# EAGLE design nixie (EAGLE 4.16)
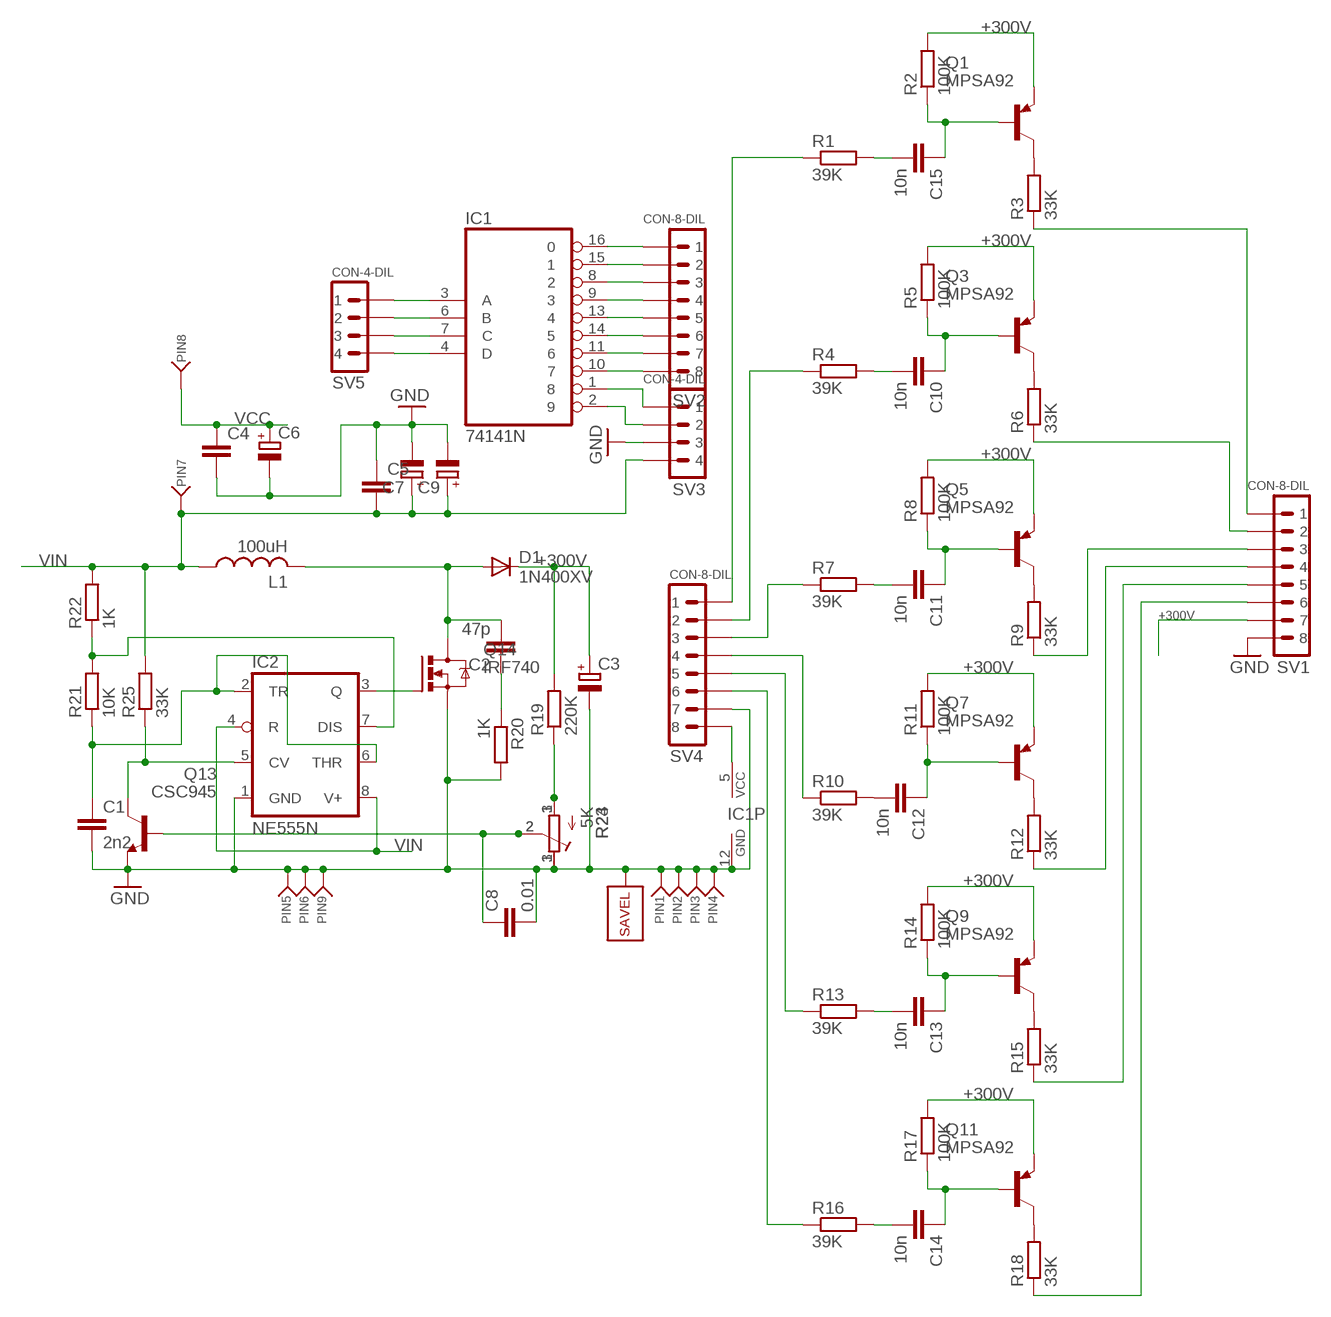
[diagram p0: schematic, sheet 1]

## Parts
C1  2n2  C-EUC0805K  [C0805K]
C2  47p  C-EU050-025X075  [C050-025X075]
C3  CPOL-EUE5-6  [E5-6]
C4  C-EUC0805K  [C0805K]
C5  C-EUC0805K  [C0805K]
C6  CPOL-EUE3.5-8  [E3,5-8]
C7  CPOL-EUE5-6  [E5-6]
C8  0.01  C-EUC0805K  [C0805K]
C9  CPOL-EUE3.5-8  [E3,5-8]
C10  10n  C-EU050-025X075  [C050-025X075]
C11  10n  C-EU050-025X075  [C050-025X075]
C12  10n  C-EU050-025X075  [C050-025X075]
C13  10n  C-EU050-025X075  [C050-025X075]
C14  10n  C-EU050-025X075  [C050-025X075]
C15  10n  C-EU050-025X075  [C050-025X075]
D1  1N400XV  [DO47-V]
IC1  74141N  [DIL16]
IC2  NE555N  [DIL08]
L1  100uH  L-US0204/7  [0204/7]
PIN1  PIN3.2  [3.2MM]
PIN2  PIN3.2  [3.2MM]
PIN3  PIN3.2  [3.2MM]
PIN4  PIN3.2  [3.2MM]
PIN5  PIN07  [PIN07]
PIN6  PINTERM_OFF  [PIN07_TERM_OFF]
PIN7  PIN07  [PIN07]
PIN8  PIN07  [PIN07]
PIN9  PINTERM_OFF  [PIN07_TERM_OFF]
Q1  MPSA92  [TO-92A]
Q3  MPSA92  [TO-92A]
Q5  MPSA92  [TO-92A]
Q7  MPSA92  [TO-92A]
Q9  MPSA92  [TO-92A]
Q11  MPSA92  [TO-92A]
Q13  CSC945  [TO-92T]
Q14  IRF740  [TO220BV]
R1  39K  R-EU_R0805  [R0805]
R2  100K  R-EU_R0805  [R0805]
R3  33K  R-EU_R0805  [R0805]
R4  39K  R-EU_R0805  [R0805]
R5  100K  R-EU_R0805  [R0805]
R6  33K  R-EU_R0805  [R0805]
R7  39K  R-EU_R0805  [R0805]
R8  100K  R-EU_R0805  [R0805]
R9  33K  R-EU_R0805  [R0805]
R10  39K  R-EU_R0805  [R0805]
R11  100K  R-EU_R0805  [R0805]
R12  33K  R-EU_R0805  [R0805]
R13  39K  R-EU_R0805  [R0805]
R14  100K  R-EU_R0805  [R0805]
R15  33K  R-EU_R0805  [R0805]
R16  39K  R-EU_R0805  [R0805]
R17  100K  R-EU_R0805  [R0805]
R18  33K  R-EU_R0805  [R0805]
R19  220K  R-EU_0204/2V  [0204V]
R20  1K  R-EU_R0805  [R0805]
R21  10K  R-EU_R0805  [R0805]
R22  1K  R-EU_R0805  [R0805]
R23  R-TRIMM3339P  [RTRIM3339P]
R24  5K  R-TRIMMT93YA  [RTRIMT93YA]
R25  33K  R-EU_R0805  [R0805]
SV1  CON-8-DIL  [CON-8-DIL-1]
SV2  CON-8-DIL  [CON-8-DIL-1]
SV3  CON-4-DIL  [CON-4-DIL-1]
SV4  CON-8-DIL  [CON-8-DIL-1]
SV5  CON-4-DIL  [CON-4-DIL-1]
U$2  SAVEL  [SAVEL]

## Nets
+300V: C3.+ D1.C Q1.E Q3.E Q5.E Q7.E Q9.E Q11.E R2.2 R5.2 R8.2 R11.2 R14.2 R17.2 R19.2 SV1.P$7
GND: C1.2 C3.- C4.2 C5.1 C6.- C7.- C8.2 C9.- IC1.12(GND) IC2.1(GND) PIN1.P$1(P) PIN2.P$1(P) PIN3.P$1(P) PIN4.P$1(P) PIN5.P$1(P) PIN6.P$1(P) PIN9.P$1(P) Q13.E Q14.S R20.2 R23.3(A) R24.1(A) SV1.P$8 SV3.P$3 SV4.P$7 U$2.P$1(A)
N$1: C15.1 Q1.B R2.1
N$2: C15.2 R1.2
N$3: IC2.3(Q) Q14.G
N$4: Q1.C R3.2
N$5: C10.1 Q3.B R5.1
N$6: C10.2 R4.2
N$7: IC2.5(CV) Q13.C R25.1
N$8: Q3.C R6.2
N$9: C11.1 Q5.B R8.1
N$10: C11.2 R7.2
N$11: C2.2 D1.A L1.2 Q14.D
N$12: Q5.C R9.2
N$13: C12.1 Q7.B R11.1
N$14: C12.2 R10.2
N$15: C2.1 R20.1
N$16: Q7.C R12.2
N$17: C13.1 Q9.B R14.1
N$18: C13.2 R13.2
N$19: IC2.7(DIS) R21.2 R22.1
N$20: Q9.C R15.2
N$21: C14.1 Q11.B R17.1
N$22: C14.2 R16.2
N$23: R19.1 R23.1(E) R24.3(E)
N$24: Q11.C R18.2
N$25: C1.1 IC2.2(TR) IC2.6(THR) R21.1
N$26: C8.1 Q13.B R23.2(S) R24.2(S)
N$27: R3.1 SV1.P$1
N$28: R6.1 SV1.P$2
N$29: R9.1 SV1.P$3
N$30: R12.1 SV1.P$4
N$31: R15.1 SV1.P$5
N$32: R18.1 SV1.P$6
N$33: IC1.16 SV2.P$1
N$34: IC1.15 SV2.P$2
N$35: IC1.8 SV2.P$3
N$36: IC1.9 SV2.P$4
N$37: IC1.13 SV2.P$5
N$38: IC1.14 SV2.P$6
N$39: IC1.11 SV2.P$7
N$40: IC1.10 SV2.P$8
N$41: IC1.1 SV3.P$1
N$42: IC1.2 SV3.P$2
N$43: R1.1 SV4.P$1
N$44: R4.1 SV4.P$2
N$45: R7.1 SV4.P$3
N$46: R10.1 SV4.P$4
N$47: R13.1 SV4.P$5
N$48: R16.1 SV4.P$6
N$49: IC1.3(A) SV5.P$1
N$50: IC1.6(B) SV5.P$2
N$51: IC1.7(C) SV5.P$3
N$52: IC1.4(D) SV5.P$4
VCC: C4.1 C6.+ IC1.5(VCC) PIN8.P$1(P) SV4.P$8
VIN: C5.2 C7.+ C9.+ IC2.4(R) IC2.8(V+) L1.1 PIN7.P$1(P) R22.2 R25.2 SV3.P$4

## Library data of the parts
C1 C2 C4 C5 C8 C10-C15 = rcl:C-EU: CAPACITOR, European symbol
C3 C6 C7 C9 = rcl:CPOL-EU: POLARIZED CAPACITOR, European symbol
D1 = LevoROMS:1N400X
IC1 = 74xx-eu:74*141: BCD to decimal DECODER/DRIVER
IC2 = linear:*555: TIMER
L1 = rcl:L-US: INDUCTOR, American symbol
PIN1-PIN9 = LevoROMS:PIN*: PIN
Q1 Q3 Q5 Q7 Q9 Q11 = LevoROMS:MPSA92
Q13 = LevoROMS:CSC945
Q14 = transistor-power:IRF740: N-CHANNEL MOS FET
R1-R22 R25 = rcl:R-EU_: RESISTOR, European symbol
R23 R24 = rcl:R-TRIMM: Trimm resistor
SV1 SV2 SV4 = LevoROMS:CON-8-DIL
SV3 SV5 = LevoROMS:CON-4-DIL
U$2 = LevoROMS:SAVEL: SAVEL

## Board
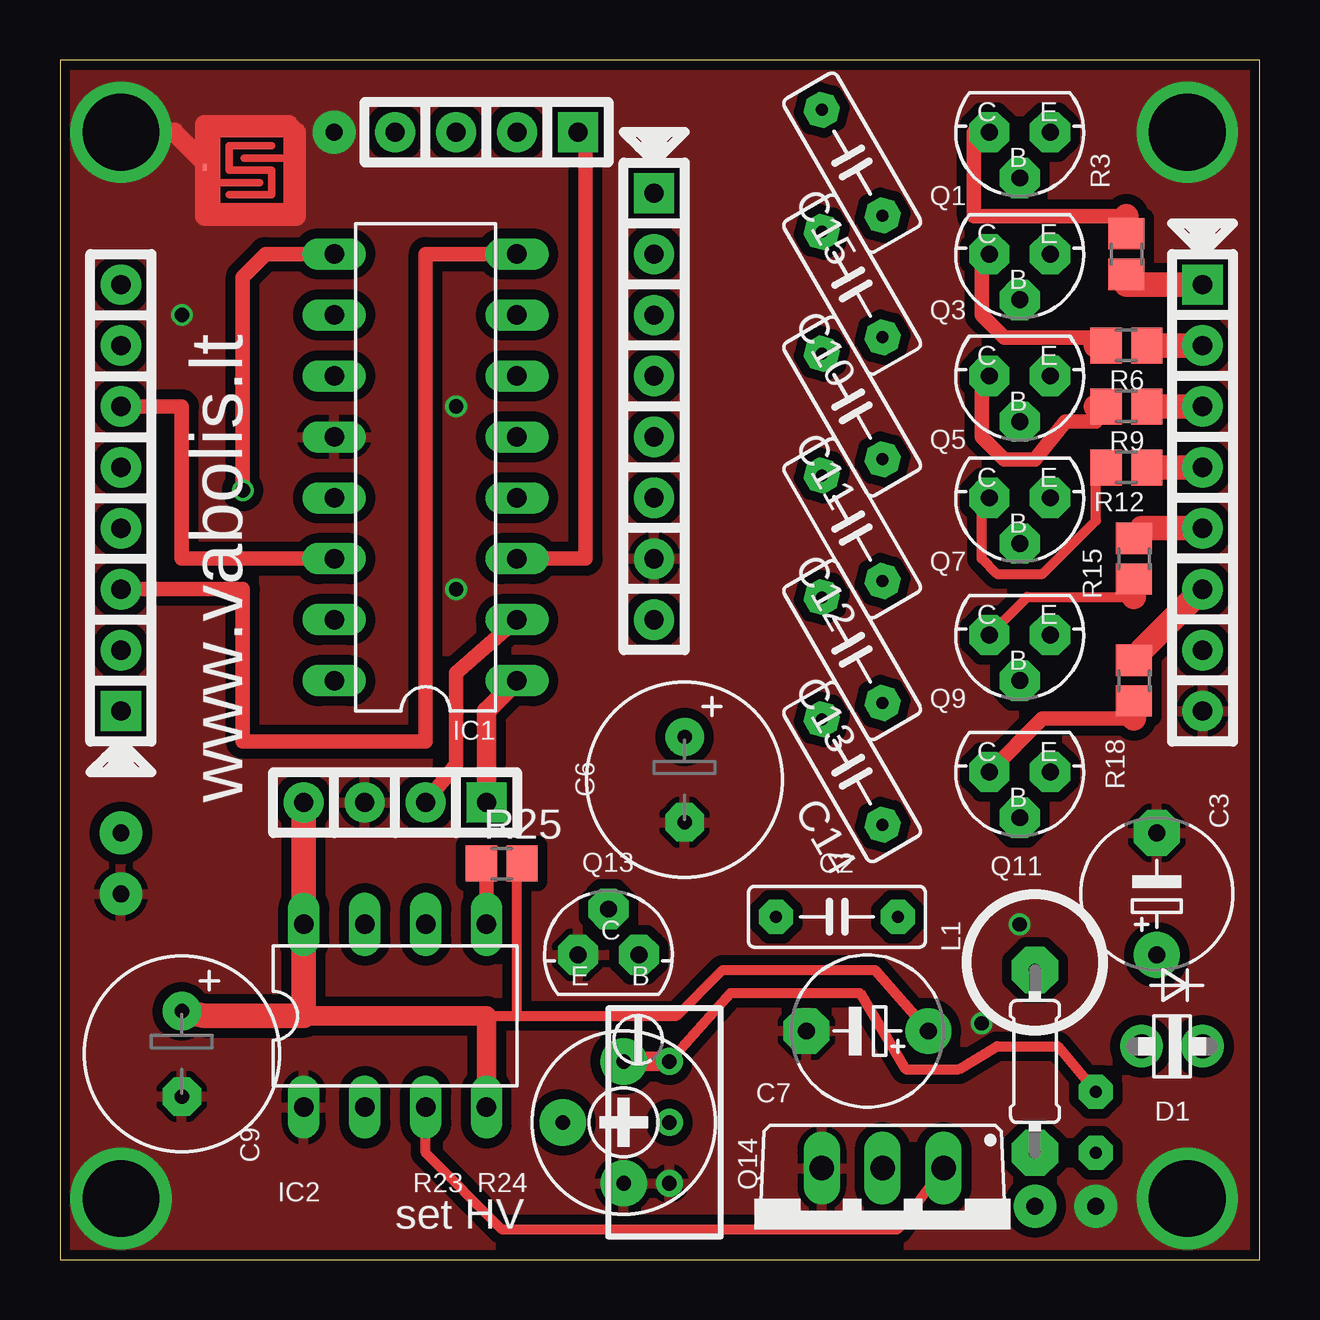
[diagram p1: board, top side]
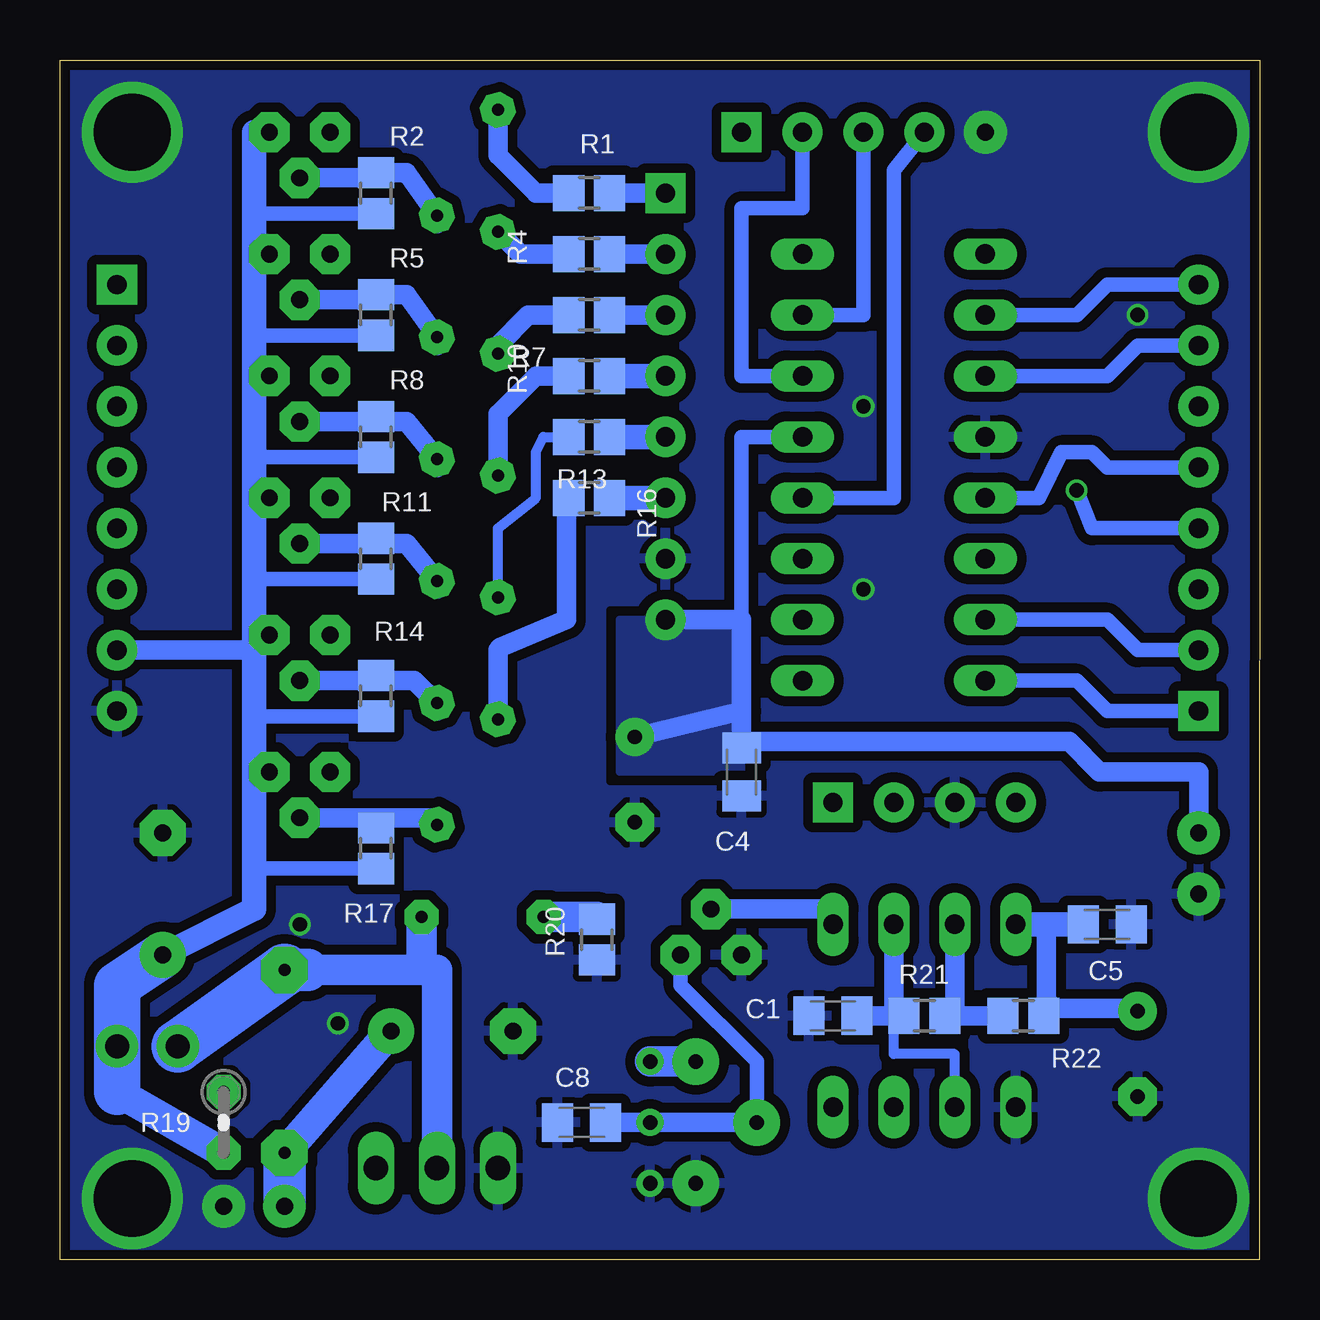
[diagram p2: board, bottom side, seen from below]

Size 50 x 50 mm. Coordinates in mm from the lower left corner, seen from the top.
Outline: 0,0 50,0 50,50 0,50 0,0
Copper layers (1*16): Top 0.035mm / dielectric 1.5mm / Bottom 0.035mm
Design rules "SeeedStudio_2layer_DRU_no_angle_20140221": minimum track width 6mil, minimum drill 12mil, track to track 6mil, track to pad 6mil, pad to pad 6mil, via to via 6mil, smd to smd 0mil, copper to edge 10mil, drill to drill 10mil, minimum pad ring 10mil, minimum via ring 6mil, stop-mask expansion 2mil, vias tented up to drill 100mil, thermal gap 10mil

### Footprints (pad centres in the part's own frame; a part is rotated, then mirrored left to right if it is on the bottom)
C0805K = smd 1.3 x 1.6: 1 -1,0; 2 1,0
C050-025X075 = drill 0.5 pad 1.422 octagon: 1 -2.54,0; 2 2.54,0
E5-6 = drill 0.7 pad 1.905 round: + -2.54,0 | drill 0.7 pad 1.905 octagon: - 2.54,0
E3,5-8 = drill 0.6 pad 1.6 round: + -1.778,0 | drill 0.6 pad 1.6 octagon: - 1.778,0
DO47-V = drill 1 pad 1.778 round: A 1.27,0; C -1.27,0
DIL16 = drill 0.813 long: 1 -8.89,-3.81; 2 -6.35,-3.81; 3 -3.81,-3.81; 4 -1.27,-3.81; 5 1.27,-3.81; 6 3.81,-3.81; 7 6.35,-3.81; 8 8.89,-3.81; 9 8.89,3.81; 10 6.35,3.81; 11 3.81,3.81; 12 1.27,3.81; 13 -1.27,3.81; 14 -3.81,3.81; 15 -6.35,3.81; 16 -8.89,3.81
DIL08 = drill 0.813 long: 1 -3.81,-3.81; 2 -1.27,-3.81; 3 1.27,-3.81; 4 3.81,-3.81; 5 3.81,3.81; 6 1.27,3.81; 7 -1.27,3.81; 8 -3.81,3.81
0204/7 = drill 0.5 pad 1.93 octagon: 1 -3.81,0; 2 3.81,0
3.2MM = drill 3.2 pad 3.81 round: P$1 0,0
PIN07 = drill 0.7 pad 1.778 round: P$1 0,0
PIN07_TERM_OFF = drill 0.7 pad 1.778 round: P$1 0,0
TO-92A = drill 0.7 pad 1.676 octagon: B 0,1.905; C 1.27,0; E -1.27,0
TO-92T = drill 0.7 pad 1.676 octagon: B 1.27,0; C 0,1.905; E -1.27,0
TO220BV = drill 1.016 long: D 0,-2.54; G -2.54,-2.54; S 2.54,-2.54
R0805 = smd 1.3 x 1.5: 1 -0.85,0; 2 0.85,0
0204V = drill 0.5 pad 1.422 octagon: 1 -1.27,0; 2 1.27,0
RTRIM3339P = drill 0.61 pad 1.93 round: 1 -2.54,0; 2 0,-2.54; 3 2.54,0
RTRIMT93YA = drill 0.61 round: 1 0,-2.54; 2 0,0; 3 0,2.54
CON-8-DIL-1 = drill 0.8 pad 1.676 square: P$1 -7.62,0 | drill 0.8 pad 1.676 round: P$2 -5.08,0; P$3 -2.54,0; P$4 0,0; P$5 2.54,0; P$6 5.08,0; P$7 7.62,0; P$8 10.16,0
CON-4-DIL-1 = drill 0.8 pad 1.676 square: P$1 -3.81,0 | drill 0.8 pad 1.676 round: P$2 -1.27,0; P$3 1.27,0; P$4 3.81,0
SAVEL = smd 0.152 x 0.305: P$1 -1.905,0.127

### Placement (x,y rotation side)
C1  17.78,10.16 180 bottom
C2  32.39,14.29 0 top
C3  45.72,15.24 90 top
C4  21.59,20.32 270 bottom
C5  6.35,13.97 180 bottom
C6  26.04,20 270 top
C7  33.66,9.53 180 top
C8  28.26,5.72 180 bottom
C9  5.08,8.57 270 top
C10  33.02,40.64 120 top
C11  33.02,35.56 120 top
C12  33.02,30.48 120 top
C13  33.02,25.4 120 top
C14  33.02,20.32 120 top
C15  33.02,45.72 120 top
D1  46.36,8.89 180 top
IC1  15.24,33.02 90 top
IC2  13.97,10.16 0 top
L1  40.64,8.26 90 top
PIN1  2.54,2.54 0 top
PIN2  46.99,2.54 0 top
PIN3  46.99,46.99 0 top
PIN4  2.54,46.99 0 top
PIN5  2.54,15.24 0 top
PIN6  43.18,2.22 0 top
PIN7  40.64,2.22 0 top
PIN8  2.54,17.78 0 top
PIN9  11.43,46.99 0 top
Q1  40.01,46.99 180 top
Q3  40.01,41.91 180 top
Q5  40.01,36.83 180 top
Q7  40.01,31.75 180 top
Q9  40.01,26.04 180 top
Q11  40.01,20.32 180 top
Q13  22.86,12.7 0 top
Q14  34.29,1.27 180 top
R1  27.94,44.45 180 bottom
R2  36.83,44.45 270 bottom
R3  44.45,41.91 90 top
R4  27.94,41.91 180 bottom
R5  36.83,39.37 270 bottom
R6  44.45,38.1 180 top
R7  27.94,39.37 180 bottom
R8  36.83,34.29 270 bottom
R9  44.45,35.56 180 top
R10  27.94,36.83 180 bottom
R11  36.83,29.21 270 bottom
R12  44.45,33.02 180 top
R13  27.94,34.29 180 bottom
R14  36.83,23.5 270 bottom
R15  44.77,29.21 270 top
R16  27.94,31.75 180 bottom
R17  36.83,17.15 270 bottom
R18  44.77,24.13 270 top
R19  43.18,5.72 270 bottom
R20  27.62,13.34 270 bottom
R21  13.97,10.16 0 bottom
R22  9.84,10.16 0 bottom
R23  23.5,5.72 270 top
R24  25.4,5.72 0 top
R25  18.42,16.51 0 top
SV1  47.63,33.02 270 top
SV2  2.54,30.48 90 top
SV3  13.97,19.05 180 top
SV4  24.77,36.83 270 top
SV5  17.78,46.99 180 top
U$2  7.94,45.4 0 top

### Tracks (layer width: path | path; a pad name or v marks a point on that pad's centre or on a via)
+300V
  Bottom 0.406: Q11.E 41.91,20.96 41.91,20.32 | 41.91,26.67 Q9.E | 41.91,31.75 Q7.E | 41.91,36.83 Q5.E | 41.91,41.91 Q3.E | 41.91,46.99 Q1.E | 41.91,27.94 41.91,28.36 | 41.91,38.1 41.91,38.52 | 41.91,43.18 41.91,43.6
  Bottom 0.61: 41.91,22.65 R14.2 | 41.91,28.36 R11.2 | 41.91,33.44 R8.2 | 41.91,38.52 R5.2 | 41.91,43.6 R2.2 | 41.91,16.3 R17.2
  Bottom 0.813: 41.91,25.4 SV1.P$7
  Bottom 1.016: C3.+ 41.91,14.61 41.91,16.3 41.91,20.32 41.91,22.65 41.91,25.4 41.91,26.67 41.91,27.94 41.91,31.75 41.91,33.02 | 41.91,33.02 41.91,36.83 41.91,38.1 41.91,41.91 41.91,43.18 41.91,46.99 | 41.91,33.02 41.91,33.44
  Bottom 1.27: R19.2 47.63,6.99
  Bottom 1.93: C3.+ 47.63,11.43 D1.C 47.63,6.99
GND  (via drill 0.6)
  Top 0.813: U$2.P$1 6.03,45.72 | 6.03,45.72 6.03,47.31 9.53,47.31 9.84,46.99 9.84,43.5 6.03,43.5 6.03,45.72 | 6.03,45.72 4.76,46.99 PIN4.P$1
  other vias: 16.51,35.56 16.51,27.94 5.08,39.37 38.42,9.84 40.01,13.97
  pour Bottom (isolate 0.406, rank 5): -8.89,55.88 55.88,55.88 55.88,-2.54 -8.89,-2.54
  pour Top (isolate 0.406, rank 5): -2.54,52.07 52.07,52.07 52.07,-1.27 -2.54,-1.27
N$1
  Bottom 0.813: 34.29,43.18 C15.1 35.56,45.3 R2.1 | R2.1 36.83,45.4 | Q1.B 36.83,45.09 R2.1
N$2
  Bottom 0.813: R1.2 30.16,44.45 31.75,46.04 C15.2
N$3
  Top 0.406: Q14.G 34.93,1.27 18.42,1.27 15.24,4.45 IC2.3
N$4
  Top 0.406: R3.2 44.45,42.55
  Top 0.61: Q1.C 38.1,46.99 38.1,43.5 44.45,43.5
  Top 1.016: 44.45,43.5 R3.2
N$5
  Bottom 0.813: 34.29,38.1 C10.1 35.56,40.22 R5.1 36.83,40.32 arc90 37.15,40.01 Q3.B
N$6
  Bottom 0.813: C10.2 31.75,42.86 30.8,41.91 R4.2
N$7
  Top 0.406: R25.1 17.78,16.51
  Top 0.61: 17.78,16.51 IC2.5
  Bottom 0.813: Q13.C 17.78,14.61 IC2.5
N$8
  Top 0.406: 38.42,41.91 Q3.C | 43.18,38.42 43.18,38.1
  Top 0.61: 38.42,41.91 38.42,39.37 39.37,38.42 43.18,38.42
  Top 1.016: 43.18,38.1 R6.2
N$9
  Bottom 0.406: 36.83,34.93 R8.1
  Bottom 0.813: Q5.B 36.83,34.93 35.56,34.93 C11.1 34.29,33.02
N$10
  Bottom 0.813: C11.2 31.75,38.1 30.48,39.37 R7.2
N$11
  Bottom 1.27: Q14.D 34.29,12.07 34.93,12.07 | 34.93,12.07 39.69,12.07 | 34.93,12.07 C2.2
  Bottom 1.778: 39.69,12.07 L1.2
  Bottom 2.184: L1.2 D1.A
N$12
  Top 0.406: 38.42,36.83 Q5.C | 43.18,34.93 43.18,35.56
  Top 0.61: 38.42,36.83 38.42,34.29 39.37,33.34 40.64,33.34 41.91,34.93 43.18,34.93
  Top 1.016: 43.18,35.56 R9.2
N$13
  Bottom 0.406: 36.83,29.85 R11.1
  Bottom 0.813: Q7.B 36.83,29.85 35.56,29.85 C12.1 34.29,27.94
N$14
  Bottom 0.813: 31.75,32.7 31.75,33.34 | R10.2 30.16,36.83 31.75,35.24 31.75,32.7 | C12.2 31.75,32.7
N$15
  Bottom 1.27: R20.1 27.62,14.29 C2.1
N$16
  Top 0.406: Q7.C 38.42,31.75 38.42,29.21 39.05,28.58 40.96,28.58 43.18,30.8 43.18,33.02 R12.2
N$17
  Bottom 0.406: 36.83,24.13 R14.1
  Bottom 0.813: Q9.B 36.83,24.13 35.24,24.13 C13.1 34.29,22.86
N$18
  Bottom 0.406: R13.2 29.85,34.29 30.16,33.66 30.16,31.75 31.75,30.48 C13.2
N$19
  Bottom 0.406: 12.7,10.16 R21.2
  Bottom 0.813: R22.1 12.7,10.16 IC2.7
N$20
  Top 0.406: Q9.C 40.32,27.62 44.77,27.62 | R15.2 45.09,28.58
  Top 1.016: 44.77,27.62 R15.2
N$21
  Bottom 0.406: 36.83,18.42 R17.1
  Bottom 0.813: Q11.B 36.83,18.42 34.29,18.42 C14.1
N$22
  Bottom 0.813: R16.2 28.89,31.75 28.89,26.67 31.65,25.5 31.75,25.4 C14.2
N$23
  Top 0.406: R19.1 41.59,8.89 39.05,8.89 37.47,7.94 35.24,7.94 33.34,11.11 27.94,11.11 R24.3
  Top 0.813: R23.1 R24.3
  Bottom 1.27: R23.1 R24.3
N$24
  Top 0.61: 44.77,22.54 40.96,22.54 Q11.C
  Top 1.016: 44.77,22.54 R18.2
N$25
  Bottom 0.406: IC2.2 12.7,8.57 15.24,8.57 15.24,10.16 R21.1
  Bottom 0.813: C1.1 15.24,10.16 IC2.6
N$26
  Bottom 0.61: R23.2 20.96,8.26 24.13,11.43 Q13.B
  Bottom 0.813: R23.2 R24.2 C8.1
N$27
  Top 0.406: R3.1 44.45,40.64
  Top 1.016: 44.45,40.64 SV1.P$1
N$28
  Top 1.016: R6.1 SV1.P$2
N$29
  Top 1.016: R9.1 SV1.P$3
N$30
  Top 1.016: R12.1 SV1.P$4
N$31
  Top 0.406: 45.09,29.85 R15.1 45.09,30.48
  Top 1.016: 45.09,30.48 SV1.P$5
N$32
  Top 0.406: R18.1 45.09,25.4
  Top 1.016: 45.09,25.4 SV1.P$6
N$33
  Bottom 0.61: IC1.16 7.62,24.13 6.35,22.86 SV2.P$1
N$34
  Bottom 0.61: IC1.15 6.35,26.67 5.08,25.4 SV2.P$2
N$35
  Top 0.61: SV2.P$3 7.62,27.94 7.62,21.59 15.24,21.59 15.24,41.91 IC1.8
N$36  (via drill 0.6)
  Top 0.61: v7.62,32.07 7.62,40.96 8.57,41.91 IC1.9
  Bottom 0.61: SV2.P$4 6.99,30.48 v7.62,32.07
N$37
  Bottom 0.61: IC1.13 9.21,31.75 8.26,33.66 6.99,33.66 6.35,33.02 SV2.P$5
N$38
  Top 0.61: SV2.P$6 5.08,35.56 5.08,29.21 IC1.14
N$39
  Bottom 0.61: IC1.11 6.35,36.83 5.08,38.1 SV2.P$7
N$40
  Bottom 0.61: IC1.10 7.62,39.37 6.35,40.64 SV2.P$8
N$41
  Top 0.813: SV3.P$1 17.78,22.86 IC1.1
N$42
  Top 0.61: IC1.2 16.51,24.45 16.51,20.64 SV3.P$2
N$43
  Bottom 0.813: SV4.P$1 R1.1
N$44
  Bottom 0.813: SV4.P$2 R4.1
N$45
  Bottom 0.813: SV4.P$3 R7.1
N$46
  Bottom 1.016: SV4.P$4 R10.1
N$47
  Bottom 1.016: SV4.P$5 R13.1
N$48
  Bottom 1.016: SV4.P$6 R16.1
N$49
  Top 0.61: IC1.3 21.91,29.21 21.91,46.67 SV5.P$1
N$50
  Bottom 0.61: IC1.6 21.59,36.83 21.59,43.82 19.05,43.82 SV5.P$2
N$51
  Bottom 0.61: IC1.7 16.51,39.37 SV5.P$3
N$52
  Bottom 0.61: IC1.4 15.24,31.75 15.24,45.4 SV5.P$4
VCC
  Bottom 0.61: IC1.5 21.59,34.29 21.59,26.67
  Bottom 0.813: SV4.P$8 21.59,26.67 21.59,22.86 | PIN8.P$1 2.54,20.32 6.67,20.32 7.94,21.59 21.59,21.59 | 21.59,21.59 21.59,22.86 | 21.59,22.86 C6.+ | 21.59,21.59 C4.1
  pour Bottom (isolate 0.406, no thermals): 21.59,26.67 21.59,20.32 26.67,20.32 26.67,26.67
VIN
  Top 0.406: C7.+ 33.97,12.07 27.62,12.07 25.72,10.16 19.05,10.16 | 17.78,10.16 19.05,10.16 | R25.2 19.05,16.51 19.05,10.16
  Top 0.813: IC2.4 17.78,10.16 10.16,10.16
  Top 1.016: SV3.P$4 IC2.8 10.16,10.16 6.03,10.16 C9.+
  Bottom 0.406: 8.89,10.16 R22.2
  Bottom 0.813: 8.89,10.8 8.89,13.97 IC2.8 | 8.89,10.8 8.89,10.16 | 5.08,10.16 5.08,10.48 8.57,10.48 8.89,10.8
  Bottom 1.016: IC2.8 C5.2
  Bottom 1.27: C7.+ L1.1
  Bottom 1.778: L1.1 PIN7.P$1

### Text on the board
tPlace: www.vabolis.lt | set HV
